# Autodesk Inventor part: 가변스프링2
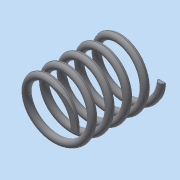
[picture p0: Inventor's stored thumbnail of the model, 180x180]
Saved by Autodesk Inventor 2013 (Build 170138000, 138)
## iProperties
Created: 2018-10
Part Number: 가변스프링2
Material: 일반
Document SubType Name: Modeling
Designer: Administrator
Density: 1 g/cm^3
Mass: 0.775357 g
Surface Area: 15.7543 cm^2
Volume: 0.775357 cm^3
Author: Administrator
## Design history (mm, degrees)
sketch "스케치1"
  geometry: L1 (0, 0)-(0, 24.745); L2 (0, 24.745)-(8, 24.745); L3 (0, 0)-(8, 0); C1 r 1 at (8, 0)
  constraints: 6 end point, 1 centre point, 1 coincident, 1 parallel, 1 perpendicular, 1 vertical
  dimensions: "d0" = 24.74499 distance of L1.start L1.end (derived); "d1" = 8 distance of L1.end L2.end; "d3" = 2 diameter of C1; "d4" = 16 diameter of L3.end L1
feature "코일1" sketch "스케치1" pitch "d5" = 10; turns "d7" = 5; dims "d6" = 24.74499 (= d0), "d8" = 0, angle "d9" = 90 deg, angle "d10" = 90 deg, "d11" = 0, "d12" = 0
sketch "스케치2"
  geometry: L1 (24.745, 10)-(0, 10); L2 (0, 10)-(0, -10); L3 (0, -10)-(24.745, -10); L4 (24.745, -10)-(24.745, 10); 2 further points
  constraints: 8 end point, 2 parallel, 1 coincident, 1 horizontal, 1 midpoint, 1 perpendicular
  dimensions: "d13" = 24.74499 distance of L2.end L3.end (derived); "d15" = 20 distance between parallel lines of L3 L1
extrude "돌출1" sketch "스케치2" stored distance "d16" = 0; taper "d17" = 0 deg
node "솔리드1"
